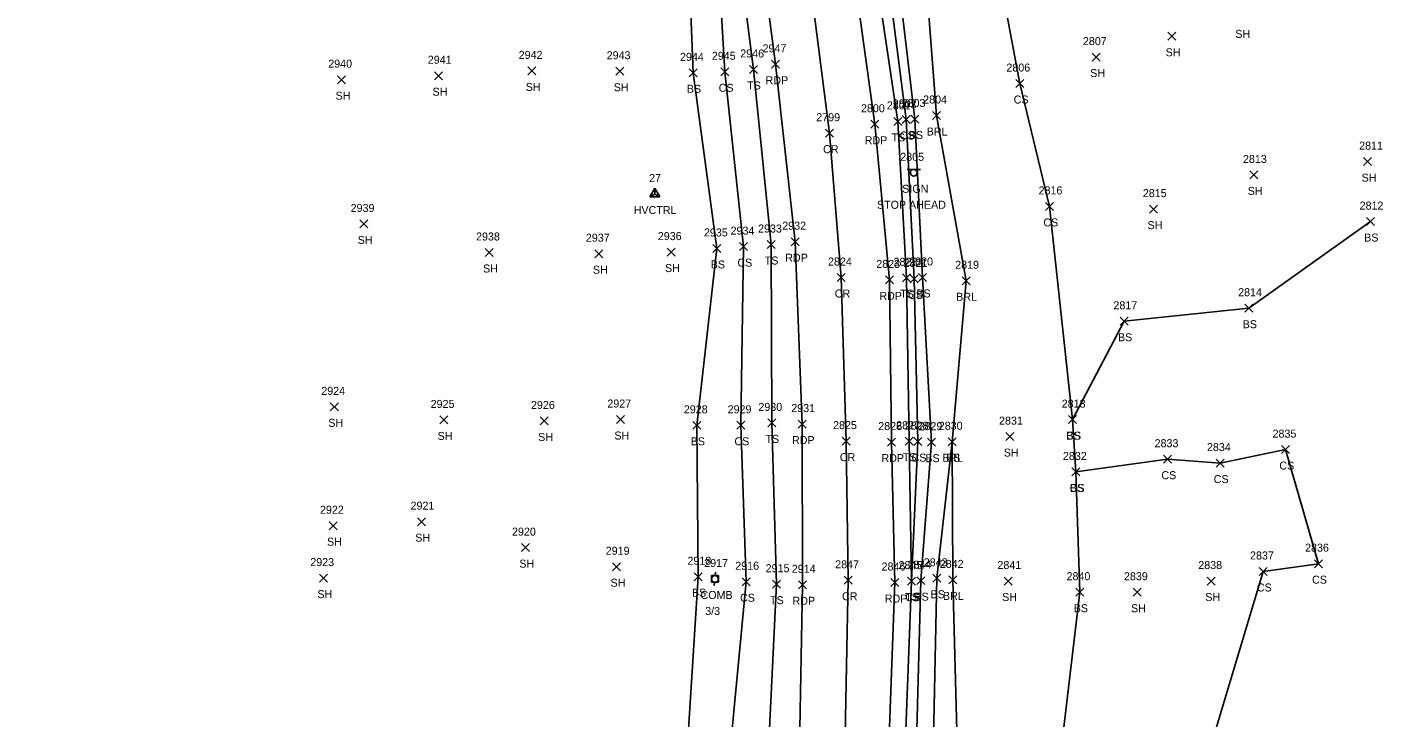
# Model space of a CAD drawing. Extents: x 1520648 to 1523413, y 732854 to 735518.
# Drawn here: x 1521781.7 to 1522120.4, y 733034.1 to 733206.8 of the extents above; entities that cross this region are included whole.
import ezdxf

# ---------------------------------------------------------------- set-up
doc = ezdxf.new("R2010")
doc.units = 0
for name, color, linetype in [('C_A', 7, 'Continuous'), ('C_I', 7, 'Continuous'), ('CPSM', 7, 'Continuous'), ('L_A', 7, 'Continuous'), ('L_I', 7, 'Continuous'), ('L_TIC', 7, 'Continuous'), ('LABL', 7, 'Continuous'), ('LELB', 7, 'Continuous'), ('P_A', 7, 'Continuous'), ('P_I', 7, 'Continuous'), ('P_TIC', 7, 'Continuous'), ('PET', 7, 'Continuous'), ('PRC', 7, 'Continuous'), ('S_A', 7, 'Continuous'), ('S_C', 7, 'Continuous'), ('S_I', 7, 'Continuous'), ('SSGN', 7, 'Continuous'), ('U_A', 7, 'Continuous'), ('U_C', 7, 'Continuous'), ('U_I', 7, 'Continuous'), ('UP', 7, 'Continuous')]:
    doc.layers.add(name, color=color, linetype=linetype)

msp = doc.modelspace()

# ---------------------------------------------------------------- linework, layer by layer
at = {"layer": 'CPSM'}
for p, q in [((1521937.32, 733164.36), (1521938.57, 733166.53)), ((1521937.32, 733164.36), (1521938.57, 733165.08)), ((1521937.32, 733164.36), (1521939.82, 733164.36)), ((1521939.82, 733164.36), (1521938.57, 733166.53)), ((1521938.57, 733165.08), (1521938.57, 733166.53)), ((1521938.57, 733165.08), (1521938.57, 733165.08)), ((1521938.57, 733165.08), (1521939.82, 733164.36))]:
    msp.add_line(p, q, dxfattribs=at)
at = {"layer": 'L_TIC'}
for points in [[(1522066.68, 733203.52), (1522068.68, 733205.52)], [(1522068.68, 733203.52), (1522066.68, 733205.52)], [(1522047.83, 733198.33), (1522049.83, 733200.33)], [(1522049.83, 733198.33), (1522047.83, 733200.33)], [(1521859.3, 733192.68), (1521861.3, 733194.68)], [(1521861.3, 733192.68), (1521859.3, 733194.68)], [(1521883.51, 733193.66), (1521885.51, 733195.66)], [(1521885.51, 733193.66), (1521883.51, 733195.66)], [(1521906.79, 733194.87), (1521908.79, 733196.87)], [(1521908.79, 733194.87), (1521906.79, 733196.87)], [(1521928.78, 733194.79), (1521930.78, 733196.79)], [(1521930.78, 733194.79), (1521928.78, 733196.79)], [(1521947.09, 733194.39), (1521949.09, 733196.39)], [(1521949.09, 733194.39), (1521947.09, 733196.39)], [(1521955.05, 733194.65), (1521957.05, 733196.65)], [(1521957.05, 733194.65), (1521955.05, 733196.65)], [(1521962.2, 733195.23), (1521964.2, 733197.23)], [(1521964.2, 733195.23), (1521962.2, 733197.23)], [(1522028.77, 733191.71), (1522030.77, 733193.71)], [(1522030.77, 733191.71), (1522028.77, 733193.71)], [(1521998.28, 733182.25), (1522000.28, 733184.25)], [(1522000.28, 733182.25), (1521998.28, 733184.25)], [(1522000.32, 733182.72), (1522002.32, 733184.72)], [(1522002.32, 733182.72), (1522000.32, 733184.72)], [(1522002.53, 733182.84), (1522004.53, 733184.84)], [(1522004.53, 733182.84), (1522002.53, 733184.84)], [(1522007.93, 733183.72), (1522009.93, 733185.72)], [(1522009.93, 733183.72), (1522007.93, 733185.72)], [(1522115.64, 733172.19), (1522117.64, 733174.19)], [(1522117.64, 733172.19), (1522115.64, 733174.19)], [(1522087.18, 733168.86), (1522089.18, 733170.86)], [(1522089.18, 733168.86), (1522087.18, 733170.86)], [(1522036.17, 733160.99), (1522038.17, 733162.99)], [(1522038.17, 733160.99), (1522036.17, 733162.99)], [(1522062.15, 733160.31), (1522064.15, 733162.31)], [(1522064.15, 733160.31), (1522062.15, 733162.31)], [(1521864.82, 733156.61), (1521866.82, 733158.61)], [(1521866.82, 733156.61), (1521864.82, 733158.61)], [(1522116.32, 733157.2), (1522118.32, 733159.2)], [(1522118.32, 733157.2), (1522116.32, 733159.2)], [(1521896.14, 733149.47), (1521898.14, 733151.47)], [(1521898.14, 733149.47), (1521896.14, 733151.47)], [(1521923.57, 733149.16), (1521925.57, 733151.16)], [(1521925.57, 733149.16), (1521923.57, 733151.16)], [(1521941.6, 733149.57), (1521943.6, 733151.57)], [(1521943.6, 733149.57), (1521941.6, 733151.57)], [(1521953.07, 733150.48), (1521955.07, 733152.48)], [(1521955.07, 733150.48), (1521953.07, 733152.48)], [(1521959.73, 733150.93), (1521961.73, 733152.93)], [(1521961.73, 733150.93), (1521959.73, 733152.93)], [(1521966.59, 733151.46), (1521968.59, 733153.46)], [(1521968.59, 733151.46), (1521966.59, 733153.46)], [(1522000.44, 733143.14), (1522002.44, 733145.14)], [(1522002.44, 733143.14), (1522000.44, 733145.14)], [(1522002.36, 733142.86), (1522004.36, 733144.86)], [(1522004.36, 733142.86), (1522002.36, 733144.86)], [(1522004.44, 733143.23), (1522006.44, 733145.23)], [(1522006.44, 733143.23), (1522004.44, 733145.23)], [(1522015.29, 733142.4), (1522017.29, 733144.4)], [(1522017.29, 733142.4), (1522015.29, 733144.4)], [(1522085.98, 733135.54), (1522087.98, 733137.54)], [(1522087.98, 733135.54), (1522085.98, 733137.54)], [(1522054.82, 733132.27), (1522056.82, 733134.27)], [(1522056.82, 733132.27), (1522054.82, 733134.27)], [(1521857.47, 733110.87), (1521859.47, 733112.87)], [(1521859.47, 733110.87), (1521857.47, 733112.87)], [(1521884.8, 733107.6), (1521886.8, 733109.6)], [(1521886.8, 733107.6), (1521884.8, 733109.6)], [(1521928.94, 733107.7), (1521930.94, 733109.7)], [(1521930.94, 733107.7), (1521928.94, 733109.7)], [(1522041.9, 733107.67), (1522043.9, 733109.67)], [(1522043.9, 733107.67), (1522041.9, 733109.67)], [(1522041.9, 733107.67), (1522043.9, 733109.67)], [(1522043.9, 733107.67), (1522041.9, 733109.67)], [(1521909.91, 733107.34), (1521911.91, 733109.34)], [(1521911.91, 733107.34), (1521909.91, 733109.34)], [(1521948.05, 733106.25), (1521950.05, 733108.25)], [(1521950.05, 733106.25), (1521948.05, 733108.25)], [(1521959, 733106.26), (1521961, 733108.26)], [(1521961, 733106.26), (1521959, 733108.26)], [(1521966.76, 733106.86), (1521968.76, 733108.86)], [(1521968.76, 733106.86), (1521966.76, 733108.86)], [(1522001.09, 733102.28), (1522003.09, 733104.28)], [(1522003.09, 733102.28), (1522001.09, 733104.28)], [(1522003.24, 733102.17), (1522005.24, 733104.17)], [(1522005.24, 733102.17), (1522003.24, 733104.17)], [(1522006.7, 733102.04), (1522008.7, 733104.04)], [(1522008.7, 733102.04), (1522006.7, 733104.04)], [(1522011.84, 733102.14), (1522013.84, 733104.14)], [(1522013.84, 733102.14), (1522011.84, 733104.14)], [(1522011.84, 733102.14), (1522013.84, 733104.14)], [(1522013.84, 733102.14), (1522011.84, 733104.14)], [(1522026.23, 733103.43), (1522028.23, 733105.43)], [(1522028.23, 733103.43), (1522026.23, 733105.43)], [(1522065.67, 733097.78), (1522067.67, 733099.78)], [(1522067.67, 733097.78), (1522065.67, 733099.78)], [(1522095.14, 733100.18), (1522097.14, 733102.18)], [(1522097.14, 733100.18), (1522095.14, 733102.18)], [(1522042.76, 733094.59), (1522044.76, 733096.59)], [(1522044.76, 733094.59), (1522042.76, 733096.59)], [(1522042.76, 733094.59), (1522044.76, 733096.59)], [(1522044.76, 733094.59), (1522042.76, 733096.59)], [(1522078.75, 733096.81), (1522080.75, 733098.81)], [(1522080.75, 733096.81), (1522078.75, 733098.81)], [(1521857.15, 733081.15), (1521859.15, 733083.15)], [(1521859.15, 733081.15), (1521857.15, 733083.15)], [(1521879.21, 733082.16), (1521881.21, 733084.16)], [(1521881.21, 733082.16), (1521879.21, 733084.16)], [(1521905.2, 733075.67), (1521907.2, 733077.67)], [(1521907.2, 733075.67), (1521905.2, 733077.67)], [(1521927.98, 733070.89), (1521929.98, 733072.89)], [(1521929.98, 733070.89), (1521927.98, 733072.89)], [(1522103.32, 733071.66), (1522105.32, 733073.66)], [(1522105.32, 733071.66), (1522103.32, 733073.66)], [(1521854.73, 733068.05), (1521856.73, 733070.05)], [(1521856.73, 733068.05), (1521854.73, 733070.05)], [(1521948.39, 733068.39), (1521950.39, 733070.39)], [(1521950.39, 733068.39), (1521948.39, 733070.39)], [(1521960.38, 733067.14), (1521962.38, 733069.14)], [(1521962.38, 733067.14), (1521960.38, 733069.14)], [(1522001.68, 733067.29), (1522003.68, 733069.29)], [(1522003.68, 733067.29), (1522001.68, 733069.29)], [(1522001.68, 733067.29), (1522003.68, 733069.29)], [(1522003.68, 733067.29), (1522001.68, 733069.29)], [(1522003.97, 733067.41), (1522005.97, 733069.41)], [(1522005.97, 733067.41), (1522003.97, 733069.41)], [(1522007.99, 733068.01), (1522009.99, 733070.01)], [(1522009.99, 733068.01), (1522007.99, 733070.01)], [(1522011.99, 733067.6), (1522013.99, 733069.6)], [(1522013.99, 733067.6), (1522011.99, 733069.6)], [(1522025.83, 733067.32), (1522027.83, 733069.32)], [(1522027.83, 733067.32), (1522025.83, 733069.32)], [(1522076.58, 733067.32), (1522078.58, 733069.32)], [(1522078.58, 733067.32), (1522076.58, 733069.32)], [(1522089.52, 733069.71), (1522091.52, 733071.71)], [(1522091.52, 733069.71), (1522089.52, 733071.71)], [(1521967.92, 733066.53), (1521969.92, 733068.53)], [(1521969.92, 733066.53), (1521967.92, 733068.53)], [(1522043.76, 733064.53), (1522045.76, 733066.53)], [(1522045.76, 733064.53), (1522043.76, 733066.53)], [(1522058.03, 733064.52), (1522060.03, 733066.52)], [(1522060.03, 733064.52), (1522058.03, 733066.52)]]:
    msp.add_lwpolyline(points, dxfattribs=at)
at = {"layer": 'LABL'}
msp.add_lwpolyline([(1522083.34, 733324.76), (1522060.94, 733340.43), (1522054.21, 733346.22), (1522026.59, 733366.47), (1522002.14, 733382.88), (1521984.92, 733392.52), (1521971.52, 733388.61), (1521986.44, 733320.81), (1521996.08, 733282.57), (1522005.56, 733228.51), (1522008.93, 733184.72), (1522016.29, 733143.4), (1522012.84, 733103.14), (1522012.99, 733068.6), (1522014.19, 733024.64), (1522012.6, 732997.91), (1522011.34, 732949.14), (1522011.36, 732900.67)], dxfattribs=at)
at = {"layer": 'LELB'}
for points in [[(1521968.22, 732870.86), (1521967.33, 732923.17), (1521965.89, 732967.63), (1521966.81, 733022.76), (1521968.92, 733067.53), (1521967.76, 733107.86), (1521967.59, 733152.46), (1521963.2, 733196.23), (1521957.56, 733240.65), (1521950.49, 733284.14), (1521942.81, 733326), (1521935.57, 733358.13), (1521922.67, 733395.52), (1521912.69, 733424.26), (1521908.68, 733436.25), (1521904.92, 733439.85), (1521900.99, 733440.9), (1521892.77, 733438.76), (1521882.33, 733431.16), (1521862.06, 733405.38), (1521836.63, 733369.94), (1521811.7, 733335.61), (1521781.71, 733295.53)], [(1521949.65, 732892.14), (1521943.39, 732922.28), (1521945.76, 732969.81), (1521946.37, 733022.02), (1521949.39, 733069.39), (1521949.05, 733107.25), (1521954.07, 733151.48), (1521948.09, 733195.39), (1521946.43, 733238.1), (1521937.33, 733283.09), (1521933.08, 733323.42), (1521926.44, 733357.1), (1521915.28, 733394.28), (1521907.45, 733416.63), (1521900.78, 733431.27), (1521903.17, 733437.88), (1521902.02, 733437.98), (1521897.59, 733434.54), (1521891.82, 733431.12), (1521884.07, 733424.19), (1521864.49, 733402.58), (1521840.1, 733367.76), (1521814.7, 733333), (1521785.26, 733292.58)], [(1521963.69, 732871.95), (1521959.51, 732890.64), (1521957.18, 732923.32), (1521956.67, 732969.02), (1521957, 733022.56), (1521961.38, 733068.14), (1521960, 733107.26), (1521960.73, 733151.93), (1521956.05, 733195.65), (1521953.46, 733239.59), (1521944.26, 733283.42), (1521938.16, 733325.19), (1521931.56, 733357.81), (1521918.99, 733395.31), (1521910.85, 733420.55), (1521908.68, 733436.25)], [(1521971.34, 733409.42), (1521966.14, 733406.97), (1521962.81, 733403.87), (1521965.17, 733387.48), (1521971.7, 733360.95), (1521975.26, 733344.26), (1521980.96, 733318.87), (1521988.64, 733282.27), (1521997.87, 733231.82), (1522003.53, 733183.84), (1522005.44, 733144.23), (1522007.7, 733103.04), (1522004.97, 733068.41), (1522003.84, 733024.82), (1522004.2, 732997.68), (1522003.06, 732946.5), (1522002.5, 732898.73)], [(1521959.04, 733407.01), (1521956.01, 733402.12), (1521959.97, 733386.6), (1521966.36, 733361.24), (1521974.27, 733317.1), (1521982.47, 733281.02), (1521992.04, 733231.94), (1521999.28, 733183.25), (1522001.44, 733144.14), (1522002.09, 733103.28), (1522002.68, 733068.29), (1522000.99, 733024.65), (1522000.58, 732997.49), (1521998.87, 732947.11), (1521999.35, 732899.05), (1521998.03, 732877.79), (1522000.79, 732870.08)], [(1521975.26, 733344.26), (1521977.99, 733318.02), (1521985.93, 733281.99), (1521995.16, 733231.79), (1522001.32, 733183.72), (1522003.36, 733143.86), (1522004.24, 733103.17), (1522002.68, 733068.29)], [(1521995.9, 733322.79), (1522009.87, 733286.44), (1522022.64, 733230.52), (1522029.77, 733192.71), (1522037.17, 733161.99), (1522042.9, 733108.67)], [(1522117.32, 733158.2), (1522086.98, 733136.54), (1522055.82, 733133.27), (1522042.9, 733108.67), (1522043.76, 733095.59), (1522044.76, 733065.53), (1522039.54, 733021.98), (1522056.41, 732989.2), (1522052.03, 732955.41)], [(1522012.84, 733103.14), (1522008.99, 733069.01), (1522008.12, 733024.87), (1522007.48, 732997.46), (1522008.3, 732948.15), (1522007.41, 732899.87)], [(1522043.76, 733095.59), (1522066.67, 733098.78), (1522079.75, 733097.81), (1522096.14, 733101.18), (1522104.32, 733072.66), (1522090.52, 733070.71), (1522076.01, 733022.36), (1522074.96, 732987.12), (1522052.03, 732955.41)]]:
    msp.add_lwpolyline(points, dxfattribs=at)
at = {"layer": 'P_TIC'}
for points in [[(1521967.72, 733196.53), (1521969.72, 733198.53)], [(1521969.72, 733196.53), (1521967.72, 733198.53)], [(1521981.15, 733179.3), (1521983.15, 733181.3)], [(1521983.15, 733179.3), (1521981.15, 733181.3)], [(1521992.48, 733181.54), (1521994.48, 733183.54)], [(1521994.48, 733181.54), (1521992.48, 733183.54)], [(1521972.64, 733152.17), (1521974.64, 733154.17)], [(1521974.64, 733152.17), (1521972.64, 733154.17)], [(1521984.07, 733143.21), (1521986.07, 733145.21)], [(1521986.07, 733143.21), (1521984.07, 733145.21)], [(1521996.14, 733142.62), (1521998.14, 733144.62)], [(1521998.14, 733142.62), (1521996.14, 733144.62)], [(1521974.32, 733106.57), (1521976.32, 733108.57)], [(1521976.32, 733106.57), (1521974.32, 733108.57)], [(1521985.34, 733102.3), (1521987.34, 733104.3)], [(1521987.34, 733102.3), (1521985.34, 733104.3)], [(1521996.69, 733102.06), (1521998.69, 733104.06)], [(1521998.69, 733102.06), (1521996.69, 733104.06)], [(1521985.87, 733067.5), (1521987.87, 733069.5)], [(1521987.87, 733067.5), (1521985.87, 733069.5)], [(1521997.51, 733066.95), (1521999.51, 733068.95)], [(1521999.51, 733066.95), (1521997.51, 733068.95)], [(1521974.46, 733066.38), (1521976.46, 733068.38)], [(1521976.46, 733066.38), (1521974.46, 733068.38)]]:
    msp.add_lwpolyline(points, dxfattribs=at)
at = {"layer": 'PET'}
for points in [[(1521970.76, 732869.72), (1521972.09, 732922.91), (1521973.57, 732966.67), (1521974.58, 733022.36), (1521975.46, 733067.38), (1521975.32, 733107.57), (1521973.64, 733153.17), (1521968.72, 733197.53), (1521962.95, 733241.68), (1521954.95, 733285.15), (1521946.27, 733327.15), (1521938.01, 733358.79), (1521928.18, 733397.9), (1521917.02, 733438.97), (1521903.82, 733481.12), (1521892.95, 733514.59), (1521880.75, 733548.75), (1521865.84, 733587.22), (1521849.85, 733622.07), (1521833.37, 733650.78), (1521822.9, 733665.59), (1521814.39, 733670.77), (1521809.29, 733673.67), (1521803.81, 733674.87)], [(1521902.8, 733554.61), (1521915.13, 733524.47), (1521924.4, 733493.77), (1521936.47, 733455.13), (1521939.79, 733444.21), (1521950.37, 733403.68), (1521961.47, 733360.28), (1521971.06, 733316.81), (1521978.45, 733280.8), (1521986.74, 733231.28), (1521993.48, 733182.54), (1521997.14, 733143.62), (1521997.69, 733103.06), (1521998.51, 733067.95), (1521996.95, 733025.03), (1521996.68, 732997.54), (1521995.07, 732947.32), (1521994.19, 732898.84), (1521993.66, 732878.59)]]:
    msp.add_lwpolyline(points, dxfattribs=at)
at = {"layer": 'PRC'}
msp.add_lwpolyline([(1521847.29, 733686.72), (1521850.2, 733676.27), (1521859.4, 733645.45), (1521868.49, 733619.43), (1521882.71, 733578.35), (1521892.3, 733552.11), (1521903.28, 733519.94), (1521912.83, 733491.67), (1521925.09, 733452.23), (1521933.2, 733423.68), (1521950.73, 733358.33), (1521960.47, 733313.72), (1521967.86, 733278.36), (1521975.83, 733229.91), (1521982.15, 733180.3), (1521985.07, 733144.21), (1521986.34, 733103.3), (1521986.87, 733068.5), (1521985.99, 733025.53), (1521985.59, 732997.69), (1521984.11, 732947.62), (1521983.04, 732898.65), (1521981.54, 732858.94)], dxfattribs=at)
at = {"layer": 'SSGN'}
for p, q in [((1522001.57, 733171.25), (1522004.9, 733171.25)), ((1522003.22, 733170.42), (1522003.22, 733170.42))]:
    msp.add_line(p, q, dxfattribs=at)
msp.add_circle((1522003.22, 733170.42), 0.833, dxfattribs=at)
at = {"layer": 'UP'}
for p, q in [((1521952.74, 733068), (1521952.74, 733069.67)), ((1521952.74, 733069.67), (1521954.41, 733069.67)), ((1521953.82, 733070.5), (1521953.57, 733069.67)), ((1521954.41, 733069.67), (1521954.41, 733068)), ((1521954.41, 733068), (1521952.74, 733068)), ((1521953.32, 733067.17), (1521953.57, 733068)), ((1521953.57, 733068.83), (1521953.57, 733068.83))]:
    msp.add_line(p, q, dxfattribs=at)
msp.add_circle((1521953.57, 733068.83), 0.833, dxfattribs=at)

# ---------------------------------------------------------------- texts
at = {"layer": 'C_A'}
msp.add_text('HVCTRL', height=2, dxfattribs=at).set_placement((1521933.26, 733160.08))
at = {"layer": 'C_I'}
msp.add_text('27', height=2, dxfattribs=at).set_placement((1521937.11, 733168.08))
at = {"layer": 'L_A'}
for s, p in [('SH', (1522083.57, 733204.13)), ('SH', (1522066.16, 733199.52)), ('SH', (1522047.32, 733194.33)), ('SH', (1521883, 733189.66)), ('SH', (1521906.28, 733190.87)), ('SH', (1521928.27, 733190.79)), ('BS', (1521946.53, 733190.39)), ('CS', (1521954.49, 733190.65)), ('TS', (1521961.61, 733191.23)), ('SH', (1521858.78, 733188.68)), ('CS', (1522028.21, 733187.71)), ('CS', (1521999.76, 733178.72)), ('BS', (1522001.97, 733178.84)), ('BRL', (1522006.47, 733179.72)), ('TS', (1521997.69, 733178.25)), ('SH', (1522115.13, 733168.19)), ('SH', (1522086.67, 733164.86)), ('CS', (1522035.61, 733156.99)), ('SH', (1522061.64, 733156.31)), ('SH', (1521864.3, 733152.61)), ('BS', (1522115.76, 733153.2)), ('SH', (1521895.63, 733145.47)), ('SH', (1521923.06, 733145.16)), ('SH', (1521941.09, 733145.57)), ('BS', (1521952.51, 733146.48)), ('CS', (1521959.18, 733146.93)), ('TS', (1521966, 733147.46)), ('TS', (1521999.84, 733139.14)), ('CS', (1522001.8, 733138.86)), ('BS', (1522003.88, 733139.23)), ('BRL', (1522013.84, 733138.4)), ('BS', (1522085.42, 733131.54)), ('BS', (1522054.26, 733128.27)), ('SH', (1521856.96, 733106.87)), ('SH', (1521884.28, 733103.6)), ('SH', (1521909.4, 733103.34)), ('SH', (1521928.43, 733103.7)), ('BS', (1521947.49, 733102.25)), ('CS', (1521958.44, 733102.26)), ('TS', (1521966.17, 733102.86)), ('CS', (1522041.34, 733103.67)), ('BS', (1522041.34, 733103.67)), ('TS', (1522000.49, 733098.28)), ('CS', (1522002.68, 733098.17)), ('BS', (1522006.14, 733098.04)), ('BRL', (1522010.38, 733098.14)), ('BS', (1522011.28, 733098.14)), ('SH', (1522025.72, 733099.43)), ('CS', (1522094.58, 733096.18)), ('CS', (1522042.2, 733090.59)), ('BS', (1522042.2, 733090.59)), ('CS', (1522065.11, 733093.78)), ('CS', (1522078.19, 733092.81)), ('SH', (1521856.64, 733077.15)), ('SH', (1521878.69, 733078.16)), ('SH', (1521904.69, 733071.67)), ('SH', (1521927.47, 733066.89)), ('CS', (1522102.76, 733067.66)), ('SH', (1521854.22, 733064.05)), ('BS', (1521947.83, 733064.39)), ('BS', (1522007.43, 733064.01)), ('BRL', (1522010.53, 733063.6)), ('CS', (1522088.96, 733065.71)), ('CS', (1521959.83, 733063.14)), ('TS', (1521967.33, 733062.53)), ('TS', (1522001.09, 733063.29)), ('CS', (1522001.12, 733063.29)), ('BS', (1522003.41, 733063.41)), ('SH', (1522025.32, 733063.32)), ('BS', (1522043.2, 733060.53)), ('SH', (1522057.51, 733060.52)), ('SH', (1522076.07, 733063.32))]:
    msp.add_text(s, height=2, dxfattribs=at).set_placement(p)
at = {"layer": 'L_I'}
for s, p in [('2807', (1522045.49, 733202.33)), ('2946', (1521959.89, 733199.23)), ('2940', (1521856.95, 733196.68)), ('2941', (1521881.82, 733197.66)), ('2942', (1521904.53, 733198.87)), ('2943', (1521926.52, 733198.79)), ('2944', (1521944.83, 733198.39)), ('2945', (1521952.79, 733198.65)), ('2806', (1522026.38, 733195.71)), ('2801', (1521996.51, 733186.25)), ('2802', (1521997.98, 733186.72)), ('2803', (1522000.2, 733186.84)), ('2804', (1522005.59, 733187.72)), ('2811', (1522114.51, 733176.19)), ('2813', (1522085.48, 733172.86)), ('2816', (1522034.42, 733164.99)), ('2815', (1522060.46, 733164.31)), ('2939', (1521862.55, 733160.61)), ('2812', (1522114.63, 733161.2)), ('2934', (1521957.47, 733154.93)), ('2933', (1521964.33, 733155.46)), ('2938', (1521893.88, 733153.47)), ('2937', (1521921.31, 733153.16)), ('2936', (1521939.29, 733153.57)), ('2935', (1521950.81, 733154.48)), ('2822', (1521998.18, 733147.14)), ('2821', (1522000.67, 733146.86)), ('2820', (1522002.09, 733147.23)), ('2819', (1522013.59, 733146.4)), ('2814', (1522084.28, 733139.54)), ('2817', (1522053.12, 733136.27)), ('2924', (1521855.21, 733114.87)), ('2925', (1521882.54, 733111.6)), ('2926', (1521907.6, 733111.34)), ('2927', (1521926.68, 733111.7)), ('2818', (1522040.2, 733111.67)), ('2818', (1522040.2, 733111.67)), ('2928', (1521945.79, 733110.25)), ('2929', (1521956.73, 733110.26)), ('2930', (1521964.42, 733110.86)), ('2827', (1521998.83, 733106.28)), ('2828', (1522000.98, 733106.17)), ('2829', (1522004.43, 733106.04)), ('2830', (1522009.49, 733106.14)), ('2830', (1522009.49, 733106.14)), ('2831', (1522024.54, 733107.43)), ('2835', (1522092.88, 733104.18)), ('2833', (1522063.41, 733101.78)), ('2834', (1522076.49, 733100.81)), ('2832', (1522040.5, 733098.59)), ('2832', (1522040.5, 733098.59)), ('2922', (1521854.89, 733085.15)), ('2921', (1521877.51, 733086.16)), ('2920', (1521902.86, 733079.67)), ('2919', (1521926.28, 733074.89)), ('2837', (1522087.26, 733073.71)), ('2836', (1522101, 733075.66)), ('2923', (1521852.47, 733072.05)), ('2918', (1521946.69, 733072.39)), ('2916', (1521958.64, 733071.14)), ('2915', (1521966.23, 733070.53)), ('2845', (1521999.42, 733071.29)), ('2845', (1521999.42, 733071.29)), ('2844', (1522001.71, 733071.41)), ('2843', (1522005.73, 733072.01)), ('2842', (1522009.73, 733071.6)), ('2841', (1522024.14, 733071.32)), ('2838', (1522074.32, 733071.32)), ('2840', (1522041.41, 733068.53)), ('2839', (1522055.76, 733068.52))]:
    msp.add_text(s, height=2, dxfattribs=at).set_placement(p)
at = {"layer": 'P_A'}
for s, p in [('RDP', (1521966.21, 733192.53)), ('CR', (1521980.58, 733175.3)), ('RDP', (1521990.97, 733177.54)), ('RDP', (1521971.12, 733148.17)), ('CR', (1521983.5, 733139.21)), ('RDP', (1521994.63, 733138.62)), ('RDP', (1521972.81, 733102.57)), ('CR', (1521984.77, 733098.3)), ('RDP', (1521995.17, 733098.06)), ('CR', (1521985.31, 733063.5)), ('RDP', (1521972.94, 733062.38)), ('RDP', (1521996, 733062.95))]:
    msp.add_text(s, height=2, dxfattribs=at).set_placement(p)
at = {"layer": 'P_I'}
for s, p in [('2947', (1521965.46, 733200.53)), ('2800', (1521990.05, 733185.54)), ('2799', (1521978.88, 733183.3)), ('2932', (1521970.38, 733156.17)), ('2824', (1521981.81, 733147.21)), ('2823', (1521993.88, 733146.62)), ('2931', (1521972.63, 733110.57)), ('2825', (1521983.08, 733106.3)), ('2826', (1521994.37, 733106.06)), ('2914', (1521972.76, 733070.38)), ('2847', (1521983.61, 733071.5)), ('2846', (1521995.2, 733070.95))]:
    msp.add_text(s, height=2, dxfattribs=at).set_placement(p)
at = {"layer": 'S_A'}
msp.add_text('SIGN', height=2, dxfattribs=at).set_placement((1522000.35, 733165.4))
at = {"layer": 'S_C'}
msp.add_text('STOP AHEAD', height=2, dxfattribs=at).set_placement((1521994.04, 733161.4))
at = {"layer": 'S_I'}
msp.add_text('2805', height=2, dxfattribs=at).set_placement((1521999.86, 733173.4))
at = {"layer": 'U_A'}
msp.add_text('COMB', height=2, dxfattribs=at).set_placement((1521949.96, 733063.83))
at = {"layer": 'U_C'}
msp.add_text('3/3', height=2, dxfattribs=at).set_placement((1521951.13, 733059.83))
at = {"layer": 'U_I'}
msp.add_text('2917', height=2, dxfattribs=at).set_placement((1521950.88, 733071.83))

doc.saveas('drawing.dxf')
